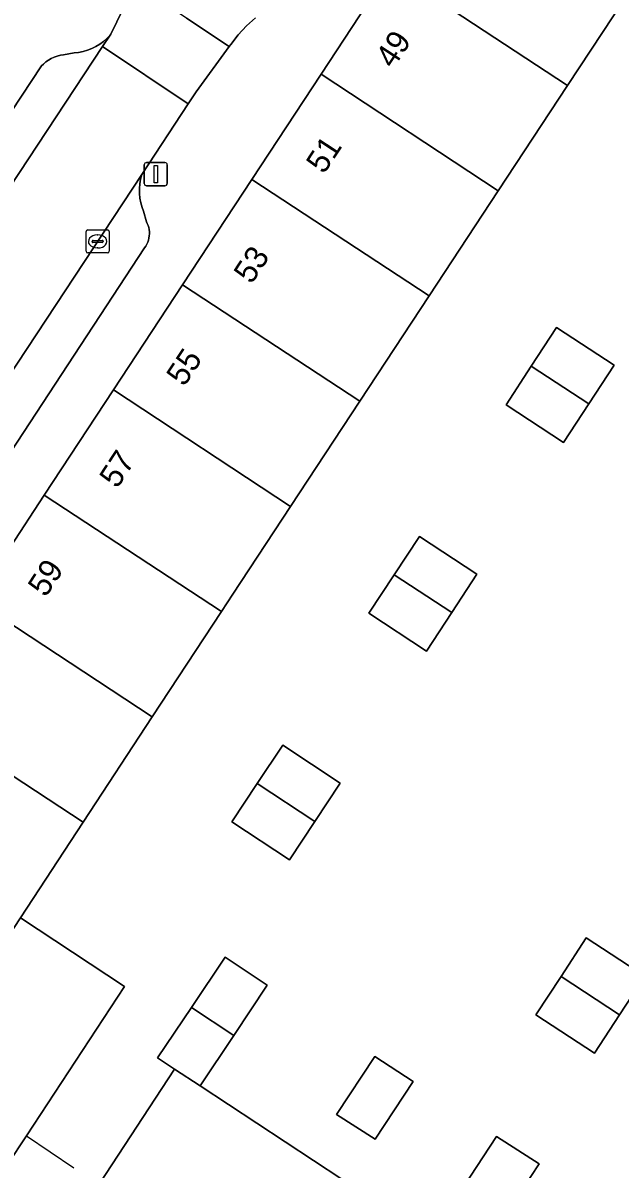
# Model space of a CAD drawing. Extents: x 159279 to 160377, y 384531 to 385888.
# Drawn here: x 159574.65 to 159600.5, y 385140.99 to 385190.61 of the extents above; entities that cross this region are included whole.
import ezdxf

# ---------------------------------------------------------------- set-up
doc = ezdxf.new("R2010")
doc.units = 0
for name, color, linetype in [('IMGEO_Erf', 7, 'Continuous'), ('IMGEO_Kolk', 7, 'Continuous'), ('IMGEO_Lichtmast', 7, 'Continuous'), ('IMGEO_Muur', 7, 'Continuous'), ('IMGEO_Pand', 7, 'Continuous'), ('IMGEO_Pand_nummerreeks', 7, 'Continuous'), ('IMGEO_Parkeervlak_open', 7, 'Continuous'), ('IMGEO_Rijbaan_lokaal_open', 7, 'Continuous'), ('IMGEO_Voetpad_open', 7, 'Continuous')]:
    doc.layers.add(name, color=color, linetype=linetype)

msp = doc.modelspace()

# ---------------------------------------------------------------- linework, layer by layer
at = {"layer": 'IMGEO_Erf'}
for points in [[(159572.578, 385165.608), (159575.573, 385170.164), (159578.568, 385174.721), (159581.563, 385179.277), (159584.558, 385183.833), (159587.553, 385188.389), (159590.548, 385192.946)], [(159601.218, 385192.462), (159598.22, 385187.903), (159595.224, 385183.347), (159592.229, 385178.791), (159589.233, 385174.235), (159586.237, 385169.679), (159583.737, 385165.877), (159583.242, 385165.123), (159580.25, 385160.565), (159577.258, 385156.006), (159574.54, 385151.865), (159579.054, 385148.896), (159574.804, 385142.432), (159573.988, 385141.19)], [(159584.722, 385190.831), (159584.328, 385190.481), (159583.968, 385190.096), (159583.643, 385189.681), (159583.575, 385189.584), (159582.156, 385187.632), (159581.809, 385187.106), (159579.793, 385184.048), (159579.741, 385183.848), (159579.706, 385183.644), (159579.69, 385183.437), (159579.693, 385183.23), (159579.714, 385183.025), (159579.753, 385182.821), (159579.811, 385182.623), (159579.872, 385182.461), (159580.002, 385181.992), (159580.032, 385181.932), (159580.067, 385181.846), (159580.094, 385181.757), (159580.113, 385181.666), (159580.124, 385181.573), (159580.127, 385181.48), (159580.121, 385181.387), (159580.107, 385181.295), (159580.085, 385181.205), (159580.055, 385181.117), (159580.017, 385181.032), (159579.971, 385180.951), (159579.919, 385180.874), (159571.346, 385167.81)], [(159577.953, 385140.341), (159581.217, 385145.312), (159580.473, 385145.801), (159581.948, 385147.988), (159583.412, 385150.158), (159585.228, 385148.955), (159583.773, 385146.772), (159582.318, 385144.589), (159588.452, 385140.56)], [(159593.721, 385140.223), (159595.154, 385142.405), (159596.995, 385141.212), (159595.555, 385139.018)]]:
    msp.add_lwpolyline(points, dxfattribs=at)
for points in [[(159599.147, 385174.118), (159598.054, 385172.449), (159595.561, 385174.082), (159596.654, 385175.751), (159597.747, 385177.42), (159600.24, 385175.787)], [(159592.115, 385163.414), (159589.625, 385165.051), (159590.72, 385166.717), (159591.815, 385168.383), (159594.305, 385166.746), (159593.21, 385165.08)], [(159588.38, 385157.702), (159587.282, 385156.043), (159586.184, 385154.383), (159583.699, 385156.027), (159584.797, 385157.687), (159585.895, 385159.346)], [(159600.478, 385147.67), (159599.385, 385146.003), (159596.848, 385147.661), (159597.942, 385149.333), (159599.031, 385150.997), (159601.571, 385149.336)], [(159589.899, 385142.282), (159588.227, 385143.356), (159589.885, 385145.87), (159591.549, 385144.782)]]:
    msp.add_lwpolyline(points, close=True, dxfattribs=at)
at = {"layer": 'IMGEO_Kolk'}
for p, q in [((159577.383, 385180.725), (159577.383, 385181.577)), ((159577.458, 385181.651), (159578.31, 385181.651)), ((159577.871, 385181.431), (159577.896, 385181.431)), ((159578.384, 385181.577), (159578.384, 385180.725)), ((159577.642, 385181.145), (159577.642, 385181.157)), ((159578.08, 385181.108), (159577.682, 385181.108)), ((159577.685, 385181.194), (159578.083, 385181.194)), ((159577.894, 385180.871), (159577.869, 385180.871)), ((159578.126, 385181.157), (159578.126, 385181.145)), ((159578.31, 385180.651), (159577.458, 385180.651))]:
    msp.add_line(p, q, dxfattribs=at)
for points in [[(159577.383, 385180.725), (159577.383, 385181.577)], [(159577.458, 385181.651), (159578.31, 385181.651)], [(159578.384, 385181.577), (159578.384, 385180.725)], [(159578.31, 385180.651), (159577.458, 385180.651)]]:
    msp.add_lwpolyline(points, dxfattribs=at)
for centre, radius, start, end in [((159577.46, 385181.575), 0.0765, 91.552, 178.448), ((159577.46, 385181.575), 0.0765, 91.552, 178.448), ((159578.308, 385181.575), 0.0765, 1.552, 88.448), ((159578.308, 385181.575), 0.0765, 1.552, 88.448), ((159577.46, 385180.727), 0.0765, 181.552, 268.448), ((159577.46, 385180.727), 0.0765, 181.552, 268.448), ((159577.682, 385181.154), 0.0403, 85.8775, 175.7526), ((159577.679, 385181.144), 0.0366, 178.938, 274.7102), ((159578.083, 385181.151), 0.043, 264.8664, 352.4533), ((159578.087, 385181.156), 0.0386, 1.7309, 96.639), ((159578.308, 385180.727), 0.0765, 271.552, 358.448), ((159578.308, 385180.727), 0.0765, 271.552, 358.448)]:
    msp.add_arc(centre, radius, start, end, dxfattribs=at)
for centre, major_axis, ratio, start_param, end_param in [((159577.87, 385181.151), (-0.387, 0.002), 0.722429, 4.712389, 7.853982), ((159577.895, 385181.151), (-0.39, 0.002), 0.717154, 1.570796, 4.712389)]:
    msp.add_ellipse(centre, major_axis=major_axis, ratio=ratio, start_param=start_param, end_param=end_param, dxfattribs=at)
at = {"layer": 'IMGEO_Lichtmast'}
for p, q in [((159579.905, 385183.664), (159579.905, 385184.464)), ((159579.905, 385184.464), (159579.905, 385183.664)), ((159580.005, 385184.564), (159580.795, 385184.564)), ((159580.795, 385184.564), (159580.005, 385184.564)), ((159580.895, 385184.464), (159580.895, 385183.664)), ((159580.895, 385183.664), (159580.895, 385184.464)), ((159580.795, 385183.564), (159580.005, 385183.564)), ((159580.005, 385183.564), (159580.795, 385183.564))]:
    msp.add_line(p, q, dxfattribs=at)
msp.add_lwpolyline([(159580.325, 385184.439), (159580.475, 385184.439), (159580.475, 385183.689), (159580.325, 385183.689), (159580.325, 385184.439)], dxfattribs=at)
for centre, start, end in [((159580.005, 385184.464), 90, 180), ((159580.005, 385184.464), 90, 180), ((159580.795, 385184.464), 0, 90), ((159580.795, 385184.464), 360, 90), ((159580.005, 385183.664), 180, 270), ((159580.005, 385183.664), 180, 270), ((159580.795, 385183.664), 270, 0), ((159580.795, 385183.664), 270, 0)]:
    msp.add_arc(centre, 0.1, start, end, dxfattribs=at)
at = {"layer": 'IMGEO_Muur'}
msp.add_lwpolyline([(159574.804, 385142.432), (159576.861, 385141.042)], dxfattribs=at)
at = {"layer": 'IMGEO_Pand'}
for points in [[(159593.543, 385197.502), (159590.548, 385192.946), (159598.22, 385187.903), (159601.218, 385192.462)], [(159590.548, 385192.946), (159587.553, 385188.389), (159595.224, 385183.347), (159598.22, 385187.903)], [(159595.224, 385183.347), (159587.553, 385188.389), (159584.558, 385183.833), (159592.229, 385178.791)], [(159592.229, 385178.791), (159584.558, 385183.833), (159581.563, 385179.277), (159589.233, 385174.235)], [(159581.563, 385179.277), (159578.568, 385174.721), (159586.237, 385169.679), (159589.233, 385174.235)], [(159600.24, 385175.787), (159597.747, 385177.42), (159596.654, 385175.751), (159599.147, 385174.118)], [(159599.147, 385174.118), (159596.654, 385175.751), (159595.561, 385174.082), (159598.054, 385172.449)], [(159578.568, 385174.721), (159575.573, 385170.164), (159583.242, 385165.123), (159583.737, 385165.877), (159586.237, 385169.679)], [(159575.573, 385170.164), (159572.578, 385165.608), (159580.25, 385160.565), (159583.242, 385165.123)], [(159594.305, 385166.746), (159591.815, 385168.383), (159590.72, 385166.717), (159593.21, 385165.08)], [(159593.21, 385165.08), (159590.72, 385166.717), (159589.625, 385165.051), (159592.115, 385163.414)], [(159572.578, 385165.608), (159569.583, 385161.052), (159577.258, 385156.006), (159580.25, 385160.565)], [(159569.583, 385161.052), (159566.588, 385156.495), (159574.266, 385151.448), (159574.54, 385151.865), (159577.258, 385156.006)], [(159588.38, 385157.702), (159585.895, 385159.346), (159584.797, 385157.687), (159587.282, 385156.043)], [(159587.282, 385156.043), (159584.797, 385157.687), (159583.699, 385156.027), (159586.184, 385154.383)], [(159579.054, 385148.896), (159574.54, 385151.865), (159574.266, 385151.448), (159571.251, 385146.854), (159569.482, 385144.159), (159573.988, 385141.19), (159574.804, 385142.432)], [(159601.571, 385149.336), (159599.031, 385150.997), (159597.942, 385149.333), (159600.478, 385147.67)], [(159585.228, 385148.955), (159583.412, 385150.158), (159581.948, 385147.988), (159583.773, 385146.772)], [(159600.478, 385147.67), (159597.942, 385149.333), (159596.848, 385147.661), (159599.385, 385146.003)], [(159583.773, 385146.772), (159581.948, 385147.988), (159580.473, 385145.801), (159581.217, 385145.312), (159582.318, 385144.589)], [(159588.227, 385143.356), (159589.899, 385142.282), (159591.549, 385144.782), (159589.885, 385145.87)], [(159588.452, 385140.56), (159582.318, 385144.589), (159581.217, 385145.312), (159577.953, 385140.341), (159585.189, 385135.581)], [(159595.154, 385142.405), (159593.721, 385140.223), (159595.555, 385139.018), (159596.995, 385141.212)]]:
    msp.add_lwpolyline(points, close=True, dxfattribs=at)
at = {"layer": 'IMGEO_Parkeervlak_open'}
for points in [[(159552.814, 385151.23), (159578.102, 385189.592), (159578.449, 385190.118), (159578.423, 385190.087), (159578.287, 385189.942), (159578.139, 385189.81), (159577.979, 385189.691), (159577.81, 385189.588), (159577.632, 385189.5), (159577.446, 385189.428), (159577.256, 385189.373), (159577.061, 385189.335), (159576.863, 385189.315), (159576.407, 385189.236), (159576.27, 385189.213), (159576.135, 385189.177), (159576.004, 385189.129), (159575.878, 385189.07), (159575.757, 385189), (159575.644, 385188.92), (159575.538, 385188.829), (159575.457, 385188.748), (159552.596, 385154.106)], [(159571.346, 385167.81), (159579.919, 385180.874), (159579.971, 385180.951), (159580.017, 385181.032), (159580.055, 385181.117), (159580.085, 385181.205), (159580.107, 385181.295), (159580.121, 385181.387), (159580.127, 385181.48), (159580.124, 385181.573), (159580.113, 385181.666), (159580.094, 385181.757), (159580.067, 385181.846), (159580.032, 385181.932), (159580.002, 385181.992), (159579.872, 385182.461), (159579.811, 385182.623), (159579.753, 385182.821), (159579.714, 385183.025), (159579.693, 385183.23), (159579.69, 385183.437), (159579.706, 385183.644), (159579.741, 385183.848), (159579.793, 385184.048), (159556.547, 385148.795)]]:
    msp.add_lwpolyline(points, dxfattribs=at)
at = {"layer": 'IMGEO_Rijbaan_lokaal_open'}
for points in [[(159581.725, 385190.818), (159579.503, 385192.301), (159578.449, 385190.118), (159578.102, 385189.592), (159581.809, 385187.106), (159582.156, 385187.632), (159583.575, 385189.584)], [(159579.793, 385184.048), (159581.809, 385187.106), (159578.102, 385189.592), (159552.814, 385151.23), (159556.547, 385148.795)]]:
    msp.add_lwpolyline(points, close=True, dxfattribs=at)
msp.add_lwpolyline([(159581.725, 385190.818), (159583.575, 385189.584), (159583.643, 385189.681), (159583.968, 385190.096), (159584.328, 385190.481), (159584.722, 385190.831)], dxfattribs=at)
at = {"layer": 'IMGEO_Voetpad_open'}
msp.add_lwpolyline([(159552.596, 385154.106), (159575.457, 385188.748), (159575.538, 385188.829), (159575.644, 385188.92), (159575.757, 385189), (159575.878, 385189.07), (159576.004, 385189.129), (159576.135, 385189.177), (159576.27, 385189.213), (159576.407, 385189.236), (159576.863, 385189.315), (159577.061, 385189.335), (159577.256, 385189.373), (159577.446, 385189.428), (159577.632, 385189.5), (159577.81, 385189.588), (159577.979, 385189.691), (159578.139, 385189.81), (159578.287, 385189.942), (159578.423, 385190.087), (159578.449, 385190.118), (159579.503, 385192.301)], dxfattribs=at)

# ---------------------------------------------------------------- texts
at = {"layer": 'IMGEO_Pand_nummerreeks'}
for s, p in [('49', (159590.679, 385188.594)), ('51', (159587.679, 385184.03)), ('53', (159584.545, 385179.263)), ('55', (159581.631, 385174.828)), ('57', (159578.73, 385170.416)), ('59', (159575.635, 385165.707))]:
    msp.add_text(s, height=1, rotation=56.6827, dxfattribs=at).set_placement(p)

doc.saveas('drawing.dxf')
